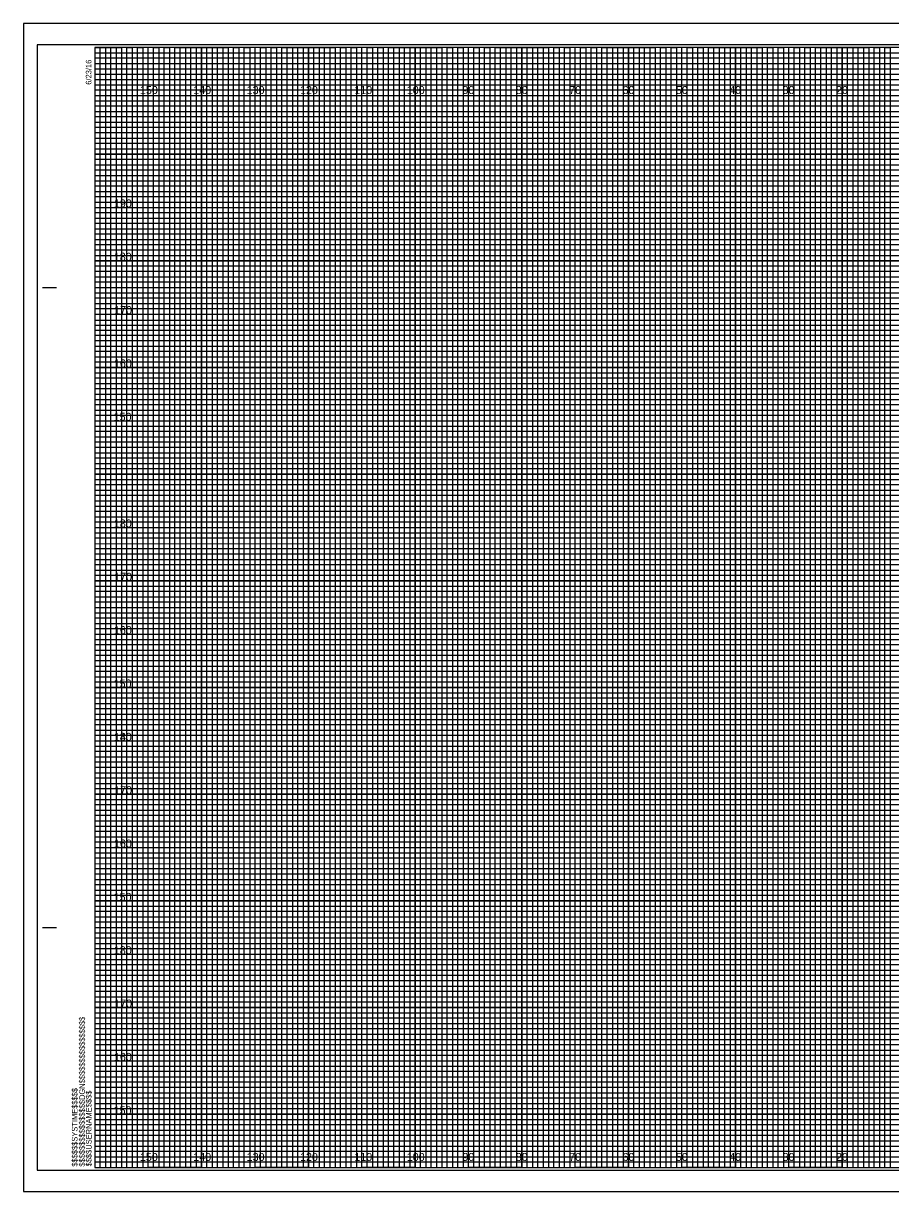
# Model space of a CAD drawing. Extents: x -13 to 323, y -5 to 434.
# Drawn here: x -13.4 to 149.1, y 215.5 to 434.5 of the extents above; entities that cross this region are included whole.
import ezdxf

# ---------------------------------------------------------------- set-up
doc = ezdxf.new("R2010")
doc.units = 0
for name, color, linetype in [('Exist Cross Section Cell', 7, 'Continuous'), ('Exist XS Center Line Elevation Label', 7, 'Continuous'), ('Exist XS Ground Line', 7, 'Continuous'), ('Prop CMT Guardrail Graphics', 7, 'Continuous'), ('Prop CMT Pvmt Course 1', 7, 'Continuous'), ('Prop CMT Pvmt Course 2', 7, 'Continuous'), ('Prop CMT Pvmt Course 3', 7, 'Continuous'), ('Prop CMT Shld Paved Course 1', 7, 'Continuous'), ('Prop CMT Shld Paved Course 2', 7, 'Continuous'), ('Prop CMT Subgrade Earthwork', 7, 'Continuous'), ('Scratch_Level_0', 7, 'Continuous')]:
    doc.layers.add(name, color=color, linetype=linetype)

msp = doc.modelspace()

# ---------------------------------------------------------------- linework, layer by layer
at = {"layer": 'Exist XS Center Line Elevation Label'}
for points in [[(0, 430), (5, 430), (5, 220), (15, 220), (15, 430), (25, 430), (25, 220), (35, 220), (35, 430), (45, 430), (45, 220), (55, 220), (55, 430), (65, 430), (65, 220), (75, 220), (75, 430), (85, 430), (85, 220), (95, 220), (95, 430), (105, 430), (105, 220), (115, 220), (115, 430), (125, 430), (125, 220), (135, 220), (135, 430), (145, 430), (145, 220), (155, 220)], [(0, 425), (275, 425)], [(0, 405), (320, 405), (320, 415), (0, 415)], [(0, 385), (320, 385), (320, 395), (0, 395)], [(0, 365), (320, 365), (320, 375), (0, 375)], [(0, 345), (320, 345), (320, 355), (0, 355)], [(0, 325), (320, 325), (320, 335), (0, 335)], [(0, 305), (320, 305), (320, 315), (0, 315)], [(0, 285), (320, 285), (320, 295), (0, 295)], [(0, 265), (320, 265), (320, 275), (0, 275)], [(0, 245), (320, 245), (320, 255), (0, 255)], [(0, 225), (320, 225), (320, 235), (0, 235)]]:
    msp.add_lwpolyline(points, dxfattribs=at)
at = {"layer": 'Exist XS Ground Line'}
for p, q in [((10, 430), (0, 430)), ((10, 220), (10, 430)), ((30, 430), (20, 430)), ((20, 430), (20, 220)), ((30, 220), (30, 430)), ((50, 430), (40, 430)), ((40, 430), (40, 220)), ((50, 220), (50, 430)), ((70, 430), (60, 430)), ((60, 430), (60, 220)), ((70, 220), (70, 430)), ((90, 430), (80, 430)), ((80, 430), (80, 220)), ((90, 220), (90, 430)), ((110, 430), (100, 430)), ((100, 430), (100, 220)), ((110, 220), (110, 430)), ((130, 430), (120, 430)), ((120, 430), (120, 220)), ((130, 220), (130, 430)), ((150, 430), (140, 430)), ((140, 430), (140, 220)), ((20, 220), (10, 220)), ((40, 220), (30, 220)), ((60, 220), (50, 220)), ((80, 220), (70, 220)), ((100, 220), (90, 220)), ((120, 220), (110, 220)), ((140, 220), (130, 220))]:
    msp.add_line(p, q, dxfattribs=at)
for points in [[(0, 420), (320, 420), (320, 410), (0, 410)], [(0, 400), (320, 400), (320, 390), (0, 390)], [(0, 380), (320, 380), (320, 370), (0, 370)], [(0, 360), (320, 360), (320, 350), (0, 350)], [(0, 340), (320, 340), (320, 330), (0, 330)], [(0, 320), (320, 320), (320, 310), (0, 310)], [(0, 300), (320, 300), (320, 290), (0, 290)], [(0, 280), (320, 280), (320, 270), (0, 270)], [(0, 260), (320, 260), (320, 250), (0, 250)], [(0, 240), (320, 240), (320, 230), (0, 230)]]:
    msp.add_lwpolyline(points, dxfattribs=at)
at = {"layer": 'Prop CMT Pvmt Course 1'}
for p, q in [((323.3, 434.5), (-13.4, 434.5)), ((-13.4, 434.5), (-13.4, 215.5)), ((-13.4, 215.5), (323.3, 215.5))]:
    msp.add_line(p, q, dxfattribs=at)
at = {"layer": 'Prop CMT Pvmt Course 2'}
msp.add_lwpolyline([(-13.4, 215.5), (323.3, 215.5), (323.3, 434.5), (-13.4, 434.5)], close=True, dxfattribs=at)
at = {"layer": 'Prop CMT Pvmt Course 3'}
msp.add_lwpolyline([(-10.8, 219.5), (322.4, 219.5), (322.4, 430.5), (-10.8, 430.5)], close=True, dxfattribs=at)
at = {"layer": 'Prop CMT Shld Paved Course 1'}
for p, q in [((-9.8, 385), (-7.3, 385)), ((-9.7, 385), (-7.2, 385)), ((-9.8, 265), (-7.3, 265)), ((-9.7, 265), (-7.2, 265)), ((0, 220), (0, 220)), ((0, 220), (0, 220)), ((0, 220), (0, 220)), ((0, 220), (0, 220)), ((0, 220), (0, 220)), ((0, 220), (0, 220)), ((0, 220), (0, 220))]:
    msp.add_line(p, q, dxfattribs=at)
msp.add_lwpolyline([(320, 430), (0, 430), (0, 220), (320, 220)], close=True, dxfattribs=at)
at = {"layer": 'Prop CMT Shld Paved Course 2'}
for points in [[(0, 220), (1, 220), (1, 430), (2, 430), (2, 220)], [(2, 220), (3, 220), (3, 430), (4, 430), (4, 220)], [(5, 220), (6, 220), (6, 430), (7, 430), (7, 220)], [(7, 220), (8, 220), (8, 430), (9, 430), (9, 220)], [(10, 220), (11, 220), (11, 430), (12, 430), (12, 220)], [(12, 220), (13, 220), (13, 430), (14, 430), (14, 220)], [(15, 220), (16, 220), (16, 430), (17, 430), (17, 220)], [(17, 220), (18, 220), (18, 430), (19, 430), (19, 220)], [(20, 220), (21, 220), (21, 430), (22, 430), (22, 220)], [(22, 220), (23, 220), (23, 430), (24, 430), (24, 220)], [(25, 220), (26, 220), (26, 430), (27, 430), (27, 220)], [(27, 220), (28, 220), (28, 430), (29, 430), (29, 220)], [(30, 220), (31, 220), (31, 430), (32, 430), (32, 220)], [(32, 220), (33, 220), (33, 430), (34, 430), (34, 220)], [(35, 220), (36, 220), (36, 430), (37, 430), (37, 220)], [(37, 220), (38, 220), (38, 430), (39, 430), (39, 220)], [(40, 220), (41, 220), (41, 430), (42, 430), (42, 220)], [(42, 220), (43, 220), (43, 430), (44, 430), (44, 220)], [(45, 220), (46, 220), (46, 430), (47, 430), (47, 220)], [(47, 220), (48, 220), (48, 430), (49, 430), (49, 220)], [(50, 220), (51, 220), (51, 430), (52, 430), (52, 220)], [(52, 220), (53, 220), (53, 430), (54, 430), (54, 220)], [(55, 220), (56, 220), (56, 430), (57, 430), (57, 220)], [(57, 220), (58, 220), (58, 430), (59, 430), (59, 220)], [(60, 220), (61, 220), (61, 430), (62, 430), (62, 220)], [(62, 220), (63, 220), (63, 430), (64, 430), (64, 220)], [(65, 220), (66, 220), (66, 430), (67, 430), (67, 220)], [(67, 220), (68, 220), (68, 430), (69, 430), (69, 220)], [(70, 220), (71, 220), (71, 430), (72, 430), (72, 220)], [(72, 220), (73, 220), (73, 430), (74, 430), (74, 220)], [(75, 220), (76, 220), (76, 430), (77, 430), (77, 220)], [(77, 220), (78, 220), (78, 430), (79, 430), (79, 220)], [(80, 220), (81, 220), (81, 430), (82, 430), (82, 220)], [(82, 220), (83, 220), (83, 430), (84, 430), (84, 220)], [(85, 220), (86, 220), (86, 430), (87, 430), (87, 220)], [(87, 220), (88, 220), (88, 430), (89, 430), (89, 220)], [(90, 220), (91, 220), (91, 430), (92, 430), (92, 220)], [(92, 220), (93, 220), (93, 430), (94, 430), (94, 220)], [(95, 220), (96, 220), (96, 430), (97, 430), (97, 220)], [(97, 220), (98, 220), (98, 430), (99, 430), (99, 220)], [(100, 220), (101, 220), (101, 430), (102, 430), (102, 220)], [(102, 220), (103, 220), (103, 430), (104, 430), (104, 220)], [(105, 220), (106, 220), (106, 430), (107, 430), (107, 220)], [(107, 220), (108, 220), (108, 430), (109, 430), (109, 220)], [(110, 220), (111, 220), (111, 430), (112, 430), (112, 220)], [(112, 220), (113, 220), (113, 430), (114, 430), (114, 220)], [(115, 220), (116, 220), (116, 430), (117, 430), (117, 220)], [(117, 220), (118, 220), (118, 430), (119, 430), (119, 220)], [(120, 220), (121, 220), (121, 430), (122, 430), (122, 220)], [(122, 220), (123, 220), (123, 430), (124, 430), (124, 220)], [(125, 220), (126, 220), (126, 430), (127, 430), (127, 220)], [(127, 220), (128, 220), (128, 430), (129, 430), (129, 220)], [(130, 220), (131, 220), (131, 430), (132, 430), (132, 220)], [(132, 220), (133, 220), (133, 430), (134, 430), (134, 220)], [(135, 220), (136, 220), (136, 430), (137, 430), (137, 220)], [(137, 220), (138, 220), (138, 430), (139, 430), (139, 220)], [(140, 220), (141, 220), (141, 430), (142, 430), (142, 220)], [(142, 220), (143, 220), (143, 430), (144, 430), (144, 220)], [(145, 220), (146, 220), (146, 430), (147, 430), (147, 220)], [(147, 220), (148, 220), (148, 430), (149, 430), (149, 220)]]:
    msp.add_lwpolyline(points, dxfattribs=at)
at = {"layer": 'Prop CMT Subgrade Earthwork'}
for p, q in [((10, 220), (10, 430)), ((20, 220), (20, 430)), ((30, 220), (30, 430)), ((40, 220), (40, 430)), ((50, 220), (50, 430)), ((60, 220), (60, 430)), ((70, 220), (70, 430)), ((80, 220), (80, 430)), ((90, 220), (90, 430)), ((100, 220), (100, 430)), ((110, 220), (110, 430)), ((120, 220), (120, 430)), ((130, 220), (130, 430)), ((140, 220), (140, 430)), ((0, 420), (320, 420)), ((0, 410), (320, 410)), ((0, 400), (320, 400)), ((0, 390), (320, 390)), ((0, 380), (320, 380)), ((0, 370), (320, 370)), ((0, 360), (320, 360)), ((0, 350), (320, 350)), ((0, 340), (320, 340)), ((0, 330), (320, 330)), ((0, 320), (320, 320)), ((0, 310), (320, 310)), ((0, 300), (320, 300)), ((0, 290), (320, 290)), ((0, 280), (320, 280)), ((0, 270), (320, 270)), ((0, 260), (320, 260)), ((0, 250), (320, 250)), ((0, 240), (320, 240)), ((0, 230), (320, 230))]:
    msp.add_line(p, q, dxfattribs=at)
at = {"layer": 'Scratch_Level_0'}
for p, q in [((0, 429), (260, 429)), ((260, 427.98), (0, 427.98)), ((0, 427.98), (0, 427)), ((0, 427), (260, 427)), ((260, 425.89), (0, 425.89)), ((0, 425.89), (0, 424)), ((0, 424), (320, 424))]:
    msp.add_line(p, q, dxfattribs=at)
for points in [[(0, 423), (270, 423), (320, 423), (320, 422), (0, 422)], [(0, 421), (320, 421), (320, 419), (0, 419)], [(0, 418), (320, 418), (320, 417), (0, 416.98)], [(0, 416), (320, 416), (320, 414), (0, 414)], [(0, 413), (320, 413), (320, 412), (0, 412)], [(0, 411), (320, 411), (320, 409), (0, 409)], [(0, 408), (320, 408), (320, 407), (0, 407)], [(0, 406), (320, 406), (320, 404), (0, 404)], [(0, 403), (320, 403), (320, 402), (0, 402)], [(0, 401), (320, 401), (320, 399), (0, 399)], [(0, 398), (320, 398), (320, 397), (0, 397)], [(0, 396), (320, 396), (320, 393.95), (320, 393), (320, 392), (0, 392)], [(0, 394), (320, 394), (320, 393), (0, 393)], [(0, 391), (320, 391), (320, 389), (0, 389.03)], [(0, 389.03), (320, 389), (320, 388), (0, 388)], [(0, 387), (320, 387), (320, 386), (0, 386)], [(0, 384), (320, 384), (320, 383), (0, 383)], [(0, 382), (320, 382), (320, 381), (0, 381)], [(-0.07, 378.89), (320, 378.89), (320, 377.88), (-0.07, 377.88)], [(0, 377), (320, 377), (320, 376), (0, 376)], [(0, 374), (320, 374), (320, 373), (0, 373)], [(0, 372), (320, 372), (320, 371), (0, 371)], [(0, 369), (320, 369), (320, 368), (0, 368)], [(0, 367), (320, 367), (320, 366), (0, 366)], [(0, 364), (320, 364), (320, 363), (0, 363)], [(0, 362), (320, 362), (320, 361), (0, 361)], [(0, 359), (320, 359), (319.99, 357.98), (0, 358)], [(0, 357), (320, 357), (320, 356), (0, 356)], [(0, 354), (320, 354), (320, 353), (0, 353)], [(0, 352), (320, 352), (320, 351), (0, 351)], [(0, 349), (320, 349), (320, 348), (0, 348)], [(0, 347), (320, 347), (320, 346), (0, 346)], [(0, 344), (320, 344), (320, 343), (0, 343)], [(0, 342), (320, 342), (320, 341), (0, 341)], [(0, 339), (320, 339), (320, 338), (0, 338)], [(0, 336.99), (320.07, 336.91), (320, 336), (0, 336)], [(0, 334), (320, 334), (320, 333), (0, 333)], [(0, 332), (320, 332), (320, 331), (0, 331)], [(0, 329), (320, 329), (320, 328), (0, 328)], [(0, 327), (320, 327), (320, 326), (0, 326)], [(0, 324), (320, 324), (320, 323), (0, 323)], [(0, 322), (320, 322), (320, 321), (0, 321)], [(0, 319), (320, 319), (320, 318), (0, 318)], [(0, 317), (320, 317), (320, 316), (0, 316)], [(0, 314), (320, 314), (320, 313), (0, 313)], [(0, 312), (320, 312), (320, 311), (0, 311)], [(0, 309), (320, 309), (320, 308), (0, 308)], [(0, 307), (320, 307), (320, 306), (0, 306)], [(0, 304), (320, 304), (320, 303), (0, 303)], [(0, 302), (320, 302), (320, 301), (0, 301)], [(0, 299), (320, 299), (319.99, 297.98), (0, 298)], [(0, 297), (320, 297), (320, 296), (0, 296)], [(0, 294), (320, 294), (320, 293), (0, 293)], [(0, 292), (320, 292), (320, 291), (0, 291)], [(0, 289), (320, 289), (320, 288), (0, 288)], [(0, 287), (320, 287), (320, 286), (0, 286)], [(0, 284), (320, 284), (320, 283), (0, 283)], [(0, 282), (320, 282), (320, 281), (0, 281)], [(0, 279), (320, 279), (320, 278), (0, 278)], [(0, 276.99), (320.07, 276.91), (320, 276), (0, 276)], [(0, 274), (320, 274), (320, 273), (0, 273)], [(0, 272), (320, 272), (320, 271), (0, 271)], [(0, 269), (320, 269), (320, 268), (0, 268)], [(0, 267), (320, 267), (320, 266), (0, 266)], [(0, 264), (320, 264), (320, 263), (0, 263)], [(0, 262), (320, 262), (320, 261), (0, 261)], [(0, 259), (320, 259), (320, 258), (0, 258)], [(0, 257), (320, 257), (320, 256), (0, 256)], [(0, 254), (320, 254), (320, 253), (0, 253)], [(0, 252), (320, 252), (320, 251), (0, 251)], [(0, 249), (320, 249), (320, 248), (0, 248)], [(0, 247), (320, 247), (320, 246), (0, 246)], [(0, 244), (320, 244), (320, 243), (0, 243)], [(0, 242), (320, 242), (320, 241), (0, 241)], [(0, 239), (320, 239), (320, 238), (0, 238)], [(0, 237), (320, 237), (320, 236), (0, 236)], [(0, 234), (320, 234), (320, 233), (0, 233)], [(0, 232), (320, 232), (320, 231), (0, 231)], [(0, 229), (320, 229), (320, 228), (0, 228)], [(0, 227), (320, 227), (320, 226), (0, 226)], [(0, 224), (320, 224), (320, 223), (0, 223)], [(0, 222), (320, 222), (320, 221), (0, 221)]]:
    msp.add_lwpolyline(points, dxfattribs=at)

# ---------------------------------------------------------------- texts
at = {"layer": 'Exist Cross Section Cell'}
for s, p in [('150', (8.44, 421.25)), ('140', (18.44, 421.25)), ('130', (28.44, 421.25)), ('120', (38.44, 421.25)), ('110', (48.62, 421.25)), ('100', (58.44, 421.25)), ('90', (68.86, 421.25)), ('80', (78.86, 421.25)), ('70', (88.86, 421.25)), ('60', (98.86, 421.25)), ('50', (108.86, 421.25)), ('40', (118.86, 421.25)), ('30', (128.86, 421.25)), ('20', (138.86, 421.25)), ('150', (8.44, 221.25)), ('140', (18.44, 221.25)), ('130', (28.44, 221.25)), ('120', (38.44, 221.25)), ('110', (48.62, 221.25)), ('100', (58.44, 221.25)), ('90', (68.86, 221.25)), ('80', (78.86, 221.25)), ('70', (88.86, 221.25)), ('60', (98.86, 221.25)), ('50', (108.86, 221.25)), ('40', (118.86, 221.25)), ('30', (128.86, 221.25)), ('20', (138.86, 221.25))]:
    msp.add_text(s, height=1.5, dxfattribs=at).set_placement(p)
at = {"layer": 'Prop CMT Guardrail Graphics'}
for s, p in [('190', (3.57, 400)), ('180', (3.55, 390)), ('170', (3.61, 380)), ('160', (3.57, 370)), ('150', (3.52, 360)), ('180', (3.55, 340)), ('170', (3.61, 330)), ('160', (3.57, 320)), ('150', (3.52, 310)), ('180', (3.55, 300)), ('140', (3.57, 300)), ('170', (3.61, 290)), ('160', (3.57, 280)), ('150', (3.52, 270)), ('180', (3.55, 260)), ('170', (3.61, 250)), ('160', (3.57, 240)), ('150', (3.52, 230))]:
    msp.add_text(s, height=1.5, dxfattribs=at).set_placement(p)
at = {"layer": 'Prop CMT Shld Paved Course 1'}
for s, p in [('6/23/16', (-0.65, 423)), ('$$$$$$$$$$$$$$$$DGN$$$$$$$$$$$$$$$$', (-1.88, 220.18)), ('$$$$$$SYSTIME$$$$$', (-3.26, 220.18)), ('$$$$USERNAME$$$$', (-0.62, 220.23))]:
    msp.add_text(s, height=1.05, rotation=90, dxfattribs=at).set_placement(p)

doc.saveas('drawing.dxf')
